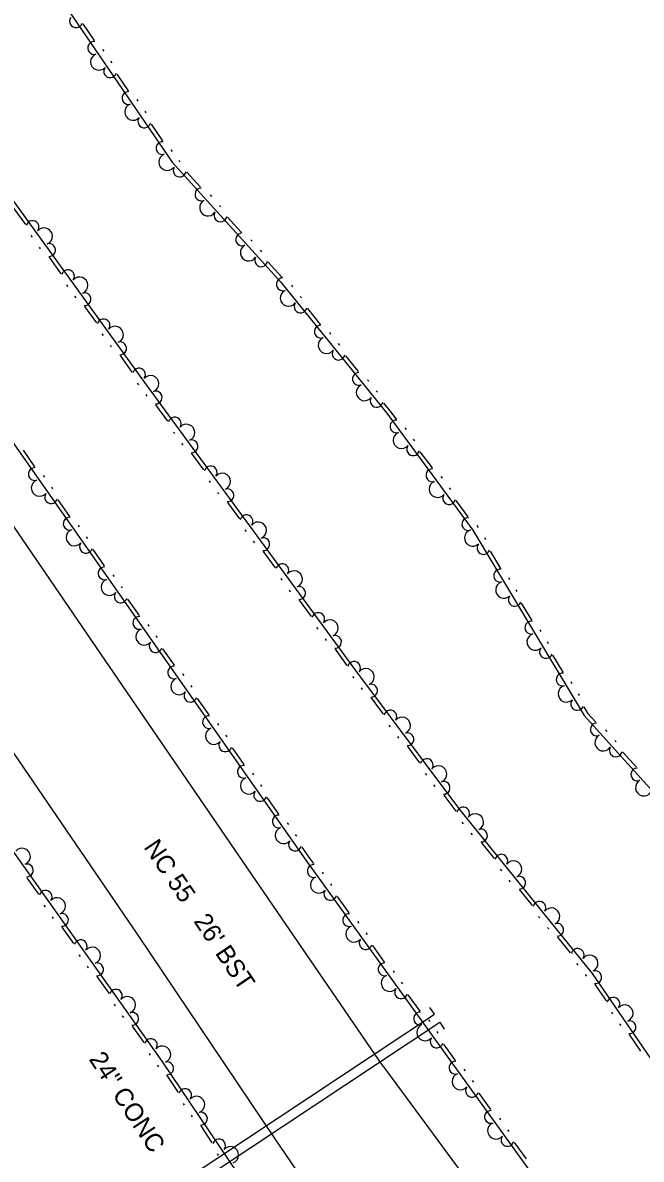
# Model space of a CAD drawing. Extents: x 2030130 to 2036320, y 723205 to 762423.
# Drawn here: x 2033639.1 to 2033764.7, y 760767.7 to 760998.3 of the extents above; entities that cross this region are included whole.
import ezdxf

# ---------------------------------------------------------------- set-up
doc = ezdxf.new("R2010")
doc.units = 0
for name, color, linetype in [('Draft_Station Labels Major', 7, 'Continuous'), ('Draft_Station Tics Major', 7, 'Continuous'), ('Draft_Station Tics Minor', 7, 'Continuous'), ('Old_Level_23', 7, 'Continuous'), ('Old_Level_26', 7, 'Continuous')]:
    doc.layers.add(name, color=color, linetype=linetype)

msp = doc.modelspace()

# ---------------------------------------------------------------- linework, layer by layer
at = {"layer": 'Draft_Station Labels Major'}
for p, q in [((2033712.22, 760786.66), (2033739.8, 760749.3)), ((2033690.27, 760771.87), (2033718.38, 760730.67))]:
    msp.add_line(p, q, dxfattribs=at)
for points in [[(2033712.22, 760786.66), (2033683.84, 760828.02), (2033655.87, 760868.99), (2033628.83, 760908.43), (2033600.16, 760950.82), (2033571.79, 760992.23), (2033543.75, 761033.03), (2033515.6, 761074.29), (2033487.47, 761115.18), (2033459.15, 761156.4), (2033430.9, 761197.59), (2033402.93, 761238.74), (2033380.71, 761271.71), (2033360.2, 761301.06), (2033346.96, 761320.77)], [(2033325.26, 761306.74), (2033353.27, 761265.49), (2033381.46, 761224.47), (2033409.65, 761183.47), (2033437.67, 761142.45), (2033465.74, 761101.32), (2033493.99, 761060.24), (2033522.13, 761019.11), (2033550.25, 760977.98), (2033578.36, 760936.85), (2033606.28, 760895.5), (2033634.33, 760854.29), (2033662.48, 760813.18), (2033690.27, 760771.87)]]:
    msp.add_lwpolyline(points, dxfattribs=at)
at = {"layer": 'Draft_Station Tics Major'}
for points in [[(2033418.93, 761226.23), (2033495.84, 761111.88), (2033561.64, 761018.79), (2033624.56, 760930.96), (2033696.62, 760828.37), (2033753.98, 760748.79), (2033771.32, 760738.45), (2033780.81, 760742.7), (2033788.33, 760748.62), (2033786.38, 760755.63), (2033780.42, 760769.02)], [(2033570.04, 761220.18), (2033566.67, 761194.48), (2033561.28, 761172.86), (2033559.34, 761154.17), (2033556.29, 761134.78), (2033557.51, 761121.08), (2033563.54, 761108.52), (2033575.34, 761091.18), (2033589.63, 761077.05), (2033606.41, 761056.51), (2033625.87, 761029.89), (2033648.44, 761000.79), (2033669.48, 760969.97), (2033691.52, 760945.68), (2033713, 760919.04), (2033730.49, 760895.32), (2033753.09, 760857.73), (2033778.45, 760829.65)], [(2033779.21, 760769.82), (2033754.79, 760805.41), (2033727.83, 760838.7), (2033706.75, 760866.89), (2033664.42, 760924.56), (2033636.24, 760963.58), (2033606.76, 761010.64), (2033581.36, 761049.61), (2033550.08, 761087.74), (2033512.77, 761135.79), (2033485.97, 761169.22), (2033454.96, 761209.86)], [(2033718.65, 760709.73), (2033694.34, 760747.74), (2033667.45, 760787.59), (2033636.39, 760831.36), (2033612.96, 760862.98), (2033578.56, 760916.73), (2033550.24, 760958.38), (2033518.84, 761006.11)], [(2033651.31, 760998.04), (2033653.62, 760994.65)], [(2033655.35, 760992.85), (2033655.58, 760992.51)], [(2033656.97, 760990.48), (2033657.2, 760990.14)], [(2033658.25, 760987.88), (2033660.56, 760984.49)], [(2033662.29, 760982.69), (2033662.52, 760982.35)], [(2033663.9, 760980.32), (2033664.14, 760979.98)], [(2033665.18, 760977.71), (2033667.5, 760974.33)], [(2033669.22, 760972.53), (2033669.45, 760972.19)], [(2033670.8, 760970.34), (2033671.08, 760970.04)], [(2033672.43, 760967.94), (2033675.19, 760964.9)], [(2033677.14, 760963.36), (2033677.42, 760963.05)], [(2033679.07, 760961.23), (2033679.35, 760960.93)], [(2033639.73, 760957.34), (2033637.33, 760960.66)], [(2033680.7, 760958.83), (2033683.45, 760955.79)], [(2033641.08, 760954.77), (2033640.84, 760955.1)], [(2033685.41, 760954.25), (2033685.69, 760953.94)], [(2033642.76, 760952.44), (2033642.52, 760952.77)], [(2033687.34, 760952.12), (2033687.61, 760951.82)], [(2033646.94, 760947.36), (2033644.54, 760950.69)], [(2033688.97, 760949.72), (2033691.72, 760946.68)], [(2033648.29, 760944.8), (2033648.05, 760945.13)], [(2033693.65, 760945.01), (2033693.9, 760944.69)], [(2033649.97, 760942.47), (2033649.73, 760942.8)], [(2033695.45, 760942.77), (2033695.7, 760942.46)], [(2033654.14, 760937.39), (2033651.74, 760940.71)], [(2033696.93, 760940.28), (2033699.5, 760937.09)], [(2033701.37, 760935.43), (2033701.62, 760935.11)], [(2033655.49, 760934.82), (2033655.25, 760935.16)], [(2033703.17, 760933.2), (2033703.43, 760932.88)], [(2033657.17, 760932.5), (2033656.93, 760932.83)], [(2033661.34, 760927.42), (2033658.94, 760930.74)], [(2033704.65, 760930.71), (2033707.22, 760927.51)], [(2033662.69, 760924.85), (2033662.45, 760925.18)], [(2033709.09, 760925.86), (2033709.35, 760925.54)], [(2033664.39, 760922.52), (2033664.15, 760922.85)], [(2033710.89, 760923.62), (2033711.15, 760923.3)], [(2033668.6, 760917.47), (2033666.17, 760920.78)], [(2033712.37, 760921.13), (2033713.65, 760919.54), (2033714.9, 760917.85)], [(2033669.97, 760914.92), (2033669.73, 760915.25)], [(2033716.69, 760916.12), (2033716.93, 760915.79)], [(2033671.67, 760912.6), (2033671.43, 760912.93)], [(2033718.39, 760913.8), (2033718.64, 760913.47)], [(2033639.19, 760911.56), (2033641.55, 760908.21)], [(2033675.88, 760907.56), (2033673.46, 760910.86)], [(2033719.76, 760911.25), (2033722.2, 760907.95)], [(2033643.3, 760906.43), (2033643.54, 760906.09)], [(2033723.99, 760906.21), (2033724.23, 760905.88)], [(2033644.95, 760904.08), (2033645.18, 760903.74)], [(2033677.25, 760905), (2033677.01, 760905.33)], [(2033725.69, 760903.9), (2033725.93, 760903.57)], [(2033646.26, 760901.49), (2033648.62, 760898.14)], [(2033678.95, 760902.68), (2033678.71, 760903.01)], [(2033683.16, 760897.64), (2033680.74, 760900.94)], [(2033727.06, 760901.35), (2033729.5, 760898.05)], [(2033650.37, 760896.36), (2033650.61, 760896.02)], [(2033731.29, 760896.31), (2033731.52, 760896), (2033731.59, 760895.88)], [(2033652.02, 760894.01), (2033652.26, 760893.67)], [(2033684.53, 760895.08), (2033684.29, 760895.41)], [(2033686.23, 760892.77), (2033685.99, 760893.1)], [(2033732.86, 760893.77), (2033733.07, 760893.42)], [(2033653.34, 760891.43), (2033655.69, 760888.07)], [(2033690.44, 760887.72), (2033688.02, 760891.03)], [(2033733.98, 760891.1), (2033736.1, 760887.58)], [(2033657.44, 760886.29), (2033657.68, 760885.96)], [(2033691.81, 760885.16), (2033691.57, 760885.5)], [(2033737.72, 760885.68), (2033737.93, 760885.33)], [(2033659.09, 760883.94), (2033659.33, 760883.61)], [(2033693.51, 760882.85), (2033693.27, 760883.18)], [(2033739.2, 760883.23), (2033739.41, 760882.87)], [(2033660.41, 760881.36), (2033662.76, 760878)], [(2033697.72, 760877.8), (2033695.3, 760881.11)], [(2033740.32, 760880.55), (2033742.44, 760877.04)], [(2033664.52, 760876.22), (2033664.75, 760875.89)], [(2033699.09, 760875.25), (2033698.85, 760875.58)], [(2033666.16, 760873.88), (2033666.4, 760873.54)], [(2033700.79, 760872.93), (2033700.55, 760873.26)], [(2033744.06, 760875.14), (2033744.27, 760874.79)], [(2033667.48, 760871.29), (2033669.84, 760867.93)], [(2033705.01, 760867.89), (2033702.58, 760871.19)], [(2033745.54, 760872.68), (2033745.75, 760872.33)], [(2033746.67, 760870.01), (2033748.78, 760866.5)], [(2033671.59, 760866.16), (2033671.82, 760865.82)], [(2033706.39, 760865.33), (2033706.14, 760865.65)], [(2033750.4, 760864.6), (2033750.61, 760864.25)], [(2033673.24, 760863.81), (2033673.47, 760863.47)], [(2033708.11, 760863.03), (2033707.86, 760863.35)], [(2033751.88, 760862.14), (2033752.09, 760861.79)], [(2033674.55, 760861.22), (2033676.91, 760857.87)], [(2033712.36, 760858.02), (2033709.91, 760861.3)], [(2033753.01, 760859.47), (2033753.76, 760858.22), (2033755.42, 760856.37)], [(2033678.66, 760856.09), (2033678.89, 760855.75)], [(2033713.76, 760855.47), (2033713.51, 760855.8)], [(2033757.38, 760854.82), (2033757.65, 760854.52)], [(2033680.31, 760853.74), (2033680.54, 760853.41)], [(2033715.47, 760853.17), (2033715.23, 760853.5)], [(2033759.3, 760852.69), (2033759.57, 760852.39)], [(2033681.62, 760851.16), (2033683.98, 760847.8)], [(2033719.73, 760848.16), (2033717.28, 760851.45)], [(2033760.92, 760850.29), (2033763.67, 760847.24)], [(2033685.73, 760846.02), (2033685.97, 760845.69)], [(2033721.12, 760845.62), (2033720.88, 760845.95)], [(2033687.38, 760843.67), (2033687.61, 760843.34)], [(2033722.84, 760843.32), (2033722.6, 760843.65)], [(2033688.69, 760841.09), (2033691.05, 760837.73)], [(2033727.1, 760838.31), (2033724.64, 760841.59)], [(2033692.8, 760835.96), (2033693.04, 760835.62)], [(2033728.6, 760835.79), (2033728.34, 760836.11)], [(2033694.45, 760833.61), (2033694.69, 760833.27)], [(2033730.41, 760833.56), (2033730.15, 760833.88)], [(2033734.86, 760828.72), (2033732.28, 760831.91)], [(2033695.77, 760831.02), (2033697.29, 760828.85), (2033698.13, 760827.68)], [(2033642.39, 760821.48), (2033640.02, 760824.83)], [(2033699.9, 760825.93), (2033700.14, 760825.59)], [(2033736.34, 760826.23), (2033736.09, 760826.55)], [(2033701.58, 760823.6), (2033701.82, 760823.27)], [(2033738.15, 760824), (2033737.89, 760824.32)], [(2033702.93, 760821.03), (2033705.33, 760817.7)], [(2033742.6, 760819.16), (2033740.02, 760822.35)], [(2033643.72, 760818.91), (2033643.48, 760819.24)], [(2033645.38, 760816.56), (2033645.15, 760816.9)], [(2033707.1, 760815.95), (2033707.34, 760815.61)], [(2033744.08, 760816.67), (2033743.83, 760816.99)], [(2033649.52, 760811.45), (2033647.14, 760814.8)], [(2033708.78, 760813.62), (2033709.02, 760813.28)], [(2033745.89, 760814.44), (2033745.63, 760814.76)], [(2033710.12, 760811.05), (2033712.52, 760807.72)], [(2033750.34, 760809.6), (2033747.76, 760812.78)], [(2033650.84, 760808.87), (2033650.6, 760809.21)], [(2033652.5, 760806.53), (2033652.27, 760806.87)], [(2033751.83, 760807.11), (2033751.57, 760807.42)], [(2033656.64, 760801.42), (2033654.26, 760804.76)], [(2033714.29, 760805.97), (2033714.53, 760805.63)], [(2033753.63, 760804.88), (2033753.38, 760805.2)], [(2033715.97, 760803.64), (2033716.21, 760803.3)], [(2033757.65, 760799.79), (2033755.33, 760803.17)], [(2033717.32, 760801.07), (2033719.71, 760797.74)], [(2033657.96, 760798.84), (2033657.73, 760799.17)], [(2033758.93, 760797.19), (2033758.7, 760797.53)], [(2033659.62, 760796.5), (2033659.39, 760796.83)], [(2033663.76, 760791.39), (2033661.38, 760794.73)], [(2033721.49, 760795.98), (2033721.73, 760795.65)], [(2033760.56, 760794.82), (2033760.33, 760795.16)], [(2033723.16, 760793.65), (2033723.4, 760793.32)], [(2033764.61, 760789.65), (2033762.29, 760793.03)], [(2033724.51, 760791.09), (2033726.91, 760787.76)], [(2033665.08, 760788.81), (2033664.85, 760789.14)], [(2033666.72, 760786.48), (2033666.49, 760786.82)], [(2033728.68, 760786), (2033728.92, 760785.67)], [(2033670.73, 760781.27), (2033668.43, 760784.67)], [(2033730.36, 760783.68), (2033730.6, 760783.34)], [(2033731.7, 760781.11), (2033734.1, 760777.78)], [(2033671.99, 760778.66), (2033671.76, 760779)], [(2033673.6, 760776.29), (2033673.37, 760776.63)], [(2033677.61, 760771.07), (2033675.32, 760774.47)], [(2033735.87, 760776.02), (2033736.11, 760775.69)], [(2033737.55, 760773.7), (2033737.79, 760773.36)], [(2033738.9, 760771.13), (2033741.3, 760767.8)], [(2033678.87, 760768.47), (2033678.64, 760768.81)]]:
    msp.add_lwpolyline(points, dxfattribs=at)
for centre, radius, start, end in [((2033649.94, 760998.59), 1.3, 142.7577, 343.5543), ((2033653.64, 760993.17), 1.3, 85.0912, 285.8878), ((2033654.58, 760990.34), 1.69, 110.2865, 318.359), ((2033656.88, 760988.43), 1.3, 142.7577, 343.5543), ((2033660.58, 760983.01), 1.3, 85.0912, 285.8878), ((2033661.52, 760980.18), 1.69, 110.2865, 318.359), ((2033663.81, 760978.27), 1.3, 142.7577, 343.5543), ((2033667.51, 760972.85), 1.3, 85.0912, 285.8878), ((2033668.45, 760970.02), 1.69, 110.2865, 318.359), ((2033670.99, 760968.3), 1.3, 150.6604, 351.4569), ((2033675.4, 760963.44), 1.3, 92.9939, 293.7905), ((2033676.73, 760960.76), 1.69, 118.1892, 326.2617), ((2033679.26, 760959.19), 1.3, 150.6604, 351.4569), ((2033641.12, 760956.82), 1.3, 324.2703, 165.0669), ((2033643.47, 760954.97), 1.69, 291.7991, 139.8716), ((2033683.67, 760954.33), 1.3, 92.9939, 293.7905), ((2033644.48, 760952.17), 1.3, 266.6038, 107.4004), ((2033684.99, 760951.65), 1.69, 118.1892, 326.2617), ((2033687.53, 760950.08), 1.3, 150.6604, 351.4569), ((2033648.32, 760946.85), 1.3, 324.2703, 165.0669), ((2033650.67, 760945), 1.69, 291.7991, 139.8716), ((2033691.91, 760945.2), 1.3, 89.6486, 290.4451), ((2033651.68, 760942.19), 1.3, 266.6038, 107.4004), ((2033693.08, 760942.45), 1.69, 114.8438, 322.9163), ((2033695.52, 760940.73), 1.3, 147.315, 348.1116), ((2033655.53, 760936.87), 1.3, 324.2703, 165.0669), ((2033657.87, 760935.02), 1.69, 291.7991, 139.8716), ((2033699.64, 760935.62), 1.3, 89.6486, 290.4451), ((2033658.89, 760932.22), 1.3, 266.6038, 107.4004), ((2033700.8, 760932.87), 1.69, 114.8438, 322.9163), ((2033703.24, 760931.15), 1.3, 147.315, 348.1116), ((2033662.73, 760926.9), 1.3, 324.2703, 165.0669), ((2033665.07, 760925.05), 1.69, 291.7991, 139.8716), ((2033707.36, 760926.04), 1.3, 89.6486, 290.4451), ((2033708.52, 760923.29), 1.69, 114.8438, 322.9163), ((2033666.11, 760922.26), 1.3, 267.0515, 107.8481), ((2033710.96, 760921.57), 1.3, 147.315, 348.1116), ((2033669.99, 760916.97), 1.3, 324.718, 165.5145), ((2033714.97, 760916.38), 1.3, 87.1626, 287.9592), ((2033672.35, 760915.14), 1.69, 292.2468, 140.3193), ((2033716.01, 760913.58), 1.69, 112.3579, 320.4304), ((2033673.39, 760912.34), 1.3, 267.0515, 107.8481), ((2033718.37, 760911.75), 1.3, 144.8291, 345.6257), ((2033641.59, 760906.73), 1.3, 85.8539, 286.6505), ((2033677.27, 760907.05), 1.3, 324.718, 165.5145), ((2033722.27, 760906.47), 1.3, 87.1626, 287.9592), ((2033642.56, 760903.91), 1.69, 111.0492, 319.1217), ((2033679.63, 760905.22), 1.69, 292.2468, 140.3193), ((2033680.67, 760902.42), 1.3, 267.0515, 107.8481), ((2033723.31, 760903.67), 1.69, 112.3579, 320.4304), ((2033644.89, 760902.03), 1.3, 143.5204, 344.317), ((2033725.67, 760901.85), 1.3, 144.8291, 345.6257), ((2033648.66, 760896.66), 1.3, 85.8539, 286.6505), ((2033684.55, 760897.13), 1.3, 324.718, 165.5145), ((2033686.91, 760895.3), 1.69, 292.2468, 140.3193), ((2033729.57, 760896.57), 1.3, 87.1626, 287.9592), ((2033649.64, 760893.84), 1.69, 111.0492, 319.1217), ((2033730.47, 760893.77), 1.69, 106.9843, 315.0568), ((2033651.96, 760891.96), 1.3, 143.5204, 344.317), ((2033687.95, 760892.5), 1.3, 267.0515, 107.8481), ((2033732.65, 760891.73), 1.3, 139.4555, 340.2521), ((2033655.73, 760886.59), 1.3, 85.8539, 286.6505), ((2033691.83, 760887.21), 1.3, 324.718, 165.5145), ((2033694.19, 760885.39), 1.69, 292.2468, 140.3193), ((2033736.03, 760886.11), 1.3, 81.789, 282.5856), ((2033656.71, 760883.77), 1.69, 111.0492, 319.1217), ((2033736.81, 760883.22), 1.69, 106.9843, 315.0568), ((2033659.03, 760881.89), 1.3, 143.5204, 344.317), ((2033695.23, 760882.59), 1.3, 267.0515, 107.8481), ((2033738.99, 760881.19), 1.3, 139.4555, 340.2521), ((2033662.8, 760876.52), 1.3, 85.8539, 286.6505), ((2033699.11, 760877.3), 1.3, 324.718, 165.5145), ((2033701.47, 760875.47), 1.69, 292.2468, 140.3193), ((2033742.37, 760875.56), 1.3, 81.789, 282.5856), ((2033663.78, 760873.7), 1.69, 111.0492, 319.1217), ((2033702.51, 760872.67), 1.3, 267.0515, 107.8481), ((2033743.15, 760872.68), 1.69, 106.9843, 315.0568), ((2033666.1, 760871.83), 1.3, 143.5204, 344.317), ((2033745.33, 760870.64), 1.3, 139.4555, 340.2521), ((2033706.39, 760867.38), 1.3, 324.718, 165.5145), ((2033669.87, 760866.46), 1.3, 85.8539, 286.6505), ((2033708.77, 760865.57), 1.69, 292.7511, 140.8236), ((2033748.71, 760865.02), 1.3, 81.789, 282.5856), ((2033670.85, 760863.64), 1.69, 111.0492, 319.1217), ((2033709.83, 760862.78), 1.3, 267.5559, 108.3524), ((2033673.17, 760861.76), 1.3, 143.5204, 344.317), ((2033749.49, 760862.14), 1.69, 106.9843, 315.0568), ((2033751.67, 760860.1), 1.3, 139.4555, 340.2521), ((2033676.94, 760856.39), 1.3, 85.8539, 286.6505), ((2033713.76, 760857.52), 1.3, 325.2223, 166.0189), ((2033716.13, 760855.71), 1.69, 292.7511, 140.8236), ((2033677.92, 760853.57), 1.69, 111.0492, 319.1217), ((2033755.64, 760854.91), 1.3, 92.8525, 293.649), ((2033680.24, 760851.69), 1.3, 143.5204, 344.317), ((2033717.2, 760852.92), 1.3, 267.5559, 108.3524), ((2033756.95, 760852.23), 1.69, 118.0477, 326.1202), ((2033759.49, 760850.65), 1.3, 150.5189, 351.3155), ((2033721.13, 760847.67), 1.3, 325.2223, 166.0189), ((2033684.02, 760846.32), 1.3, 85.8539, 286.6505), ((2033723.5, 760845.86), 1.69, 292.7511, 140.8236), ((2033763.88, 760845.78), 1.3, 92.8525, 293.649), ((2033684.99, 760843.5), 1.69, 111.0492, 319.1217), ((2033724.56, 760843.07), 1.3, 267.5559, 108.3524), ((2033765.2, 760843.1), 1.69, 118.0477, 326.1202), ((2033687.32, 760841.62), 1.3, 143.5204, 344.317), ((2033728.53, 760837.84), 1.3, 327.4288, 168.2254), ((2033691.09, 760836.25), 1.3, 85.8539, 286.6505), ((2033730.97, 760836.13), 1.69, 294.9576, 143.0301), ((2033692.07, 760833.43), 1.69, 111.0492, 319.1217), ((2033732.14, 760833.38), 1.3, 269.7624, 110.5589), ((2033694.39, 760831.56), 1.3, 143.5204, 344.317), ((2033638.99, 760829.12), 1.69, 291.3276, 139.4001), ((2033736.27, 760828.28), 1.3, 327.4288, 168.2254), ((2033639.98, 760826.31), 1.3, 266.1323, 106.9289), ((2033698.19, 760826.2), 1.3, 86.5519, 287.3484), ((2033738.71, 760826.57), 1.69, 294.9576, 143.0301), ((2033699.2, 760823.4), 1.69, 111.7471, 319.8196), ((2033739.88, 760823.82), 1.3, 269.7624, 110.5589), ((2033643.78, 760820.96), 1.3, 323.7988, 164.5953), ((2033646.11, 760819.09), 1.69, 291.3276, 139.4001), ((2033701.54, 760821.55), 1.3, 144.2183, 345.0149), ((2033744.01, 760818.72), 1.3, 327.4288, 168.2254), ((2033746.45, 760817), 1.69, 294.9576, 143.0301), ((2033647.1, 760816.27), 1.3, 266.1323, 106.9289), ((2033705.38, 760816.22), 1.3, 86.5519, 287.3484), ((2033747.62, 760814.26), 1.3, 269.7624, 110.5589), ((2033706.39, 760813.42), 1.69, 111.7471, 319.8196), ((2033650.9, 760810.92), 1.3, 323.7988, 164.5953), ((2033708.74, 760811.57), 1.3, 144.2183, 345.0149), ((2033653.23, 760809.06), 1.69, 291.3276, 139.4001), ((2033751.75, 760809.16), 1.3, 327.4288, 168.2254), ((2033754.2, 760807.44), 1.69, 294.9576, 143.0301), ((2033654.22, 760806.24), 1.3, 266.1323, 106.9289), ((2033712.57, 760806.24), 1.3, 86.5519, 287.3484), ((2033713.59, 760803.44), 1.69, 111.7471, 319.8196), ((2033755.31, 760804.65), 1.3, 265.2305, 106.0271), ((2033658.02, 760800.89), 1.3, 323.7988, 164.5953), ((2033715.93, 760801.59), 1.3, 144.2183, 345.0149), ((2033660.35, 760799.02), 1.69, 291.3276, 139.4001), ((2033759.02, 760799.24), 1.3, 322.897, 163.6936), ((2033661.34, 760796.21), 1.3, 266.1323, 106.9289), ((2033719.77, 760796.26), 1.3, 86.5519, 287.3484), ((2033761.32, 760797.34), 1.69, 290.4258, 138.4983), ((2033720.78, 760793.45), 1.69, 111.7471, 319.8196), ((2033762.27, 760794.51), 1.3, 265.2305, 106.0271), ((2033665.14, 760790.86), 1.3, 323.7988, 164.5953), ((2033667.47, 760788.99), 1.69, 291.3276, 139.4001), ((2033723.13, 760791.61), 1.3, 144.2183, 345.0149), ((2033668.43, 760786.15), 1.3, 264.7755, 105.5721), ((2033726.96, 760786.28), 1.3, 86.5519, 287.3484), ((2033727.98, 760783.47), 1.69, 111.7471, 319.8196), ((2033672.1, 760780.71), 1.3, 322.442, 163.2386), ((2033730.32, 760781.62), 1.3, 144.2183, 345.0149), ((2033674.38, 760778.79), 1.69, 289.9708, 138.0433), ((2033675.31, 760775.95), 1.3, 264.7755, 105.5721), ((2033734.16, 760776.3), 1.3, 86.5519, 287.3484), ((2033735.17, 760773.49), 1.69, 111.7471, 319.8196), ((2033678.98, 760770.51), 1.3, 322.442, 163.2386), ((2033737.51, 760771.64), 1.3, 144.2183, 345.0149), ((2033681.26, 760768.59), 1.69, 289.9708, 138.0433)]:
    msp.add_arc(centre, radius, start, end, dxfattribs=at)
at = {"layer": 'Draft_Station Tics Minor'}
for p, q in [((2033722.68, 760797.14), (2033721.78, 760798.51)), ((2033723.77, 760795.5), (2033724.68, 760794.13))]:
    msp.add_line(p, q, dxfattribs=at)
for points in [[(2033665.24, 760759.07), (2033722.68, 760797.14)], [(2033666.32, 760757.43), (2033723.77, 760795.5)]]:
    msp.add_lwpolyline(points, dxfattribs=at)

# ---------------------------------------------------------------- texts
at = {"layer": 'Old_Level_23'}
msp.add_text("NC 55   26' BST", height=3.6909, rotation=304.0128, dxfattribs=at).set_placement((2033663.57, 760831.02))
at = {"layer": 'Old_Level_26'}
msp.add_text('24" CONC', height=3.691, rotation=303.3771, dxfattribs=at).set_placement((2033652.45, 760788.02))

doc.saveas('drawing.dxf')
